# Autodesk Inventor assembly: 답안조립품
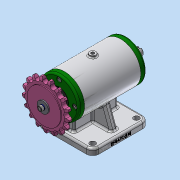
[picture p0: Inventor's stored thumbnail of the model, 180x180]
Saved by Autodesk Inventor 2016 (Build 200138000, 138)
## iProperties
Created: 2019-06
Part Number: 답안조립품
Material: 일반
Document SubType Name: Assembly
Designer: Administrator
Author: Administrator
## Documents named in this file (11)
- C:\Users\Administrator\Desktop\490604V1019\답안조립품.iam
- C:\Users\Administrator\Desktop\490604V1019\본체.ipt
- C:\Users\Administrator\Desktop\490604V1019\커버.ipt
- C:\Users\Administrator\Desktop\490604V1019\베어링 6203.ipt
- C:\Users\Administrator\Desktop\490604V1019\축.ipt
- C:\Users\Administrator\Desktop\490604V1019\오일 실 17 30 5.ipt
- C:\Users\Administrator\Desktop\490604V1019\스프로킷.ipt
- C:\Users\Administrator\Desktop\490604V1019\키 4x4x12.ipt
- C:\Users\Administrator\Desktop\490604V1019\평와셔.ipt
- C:\Users\Administrator\Desktop\490604V1019\스프링와셔.ipt
- C:\Users\Administrator\Desktop\490604V1019\볼트 M4.ipt
